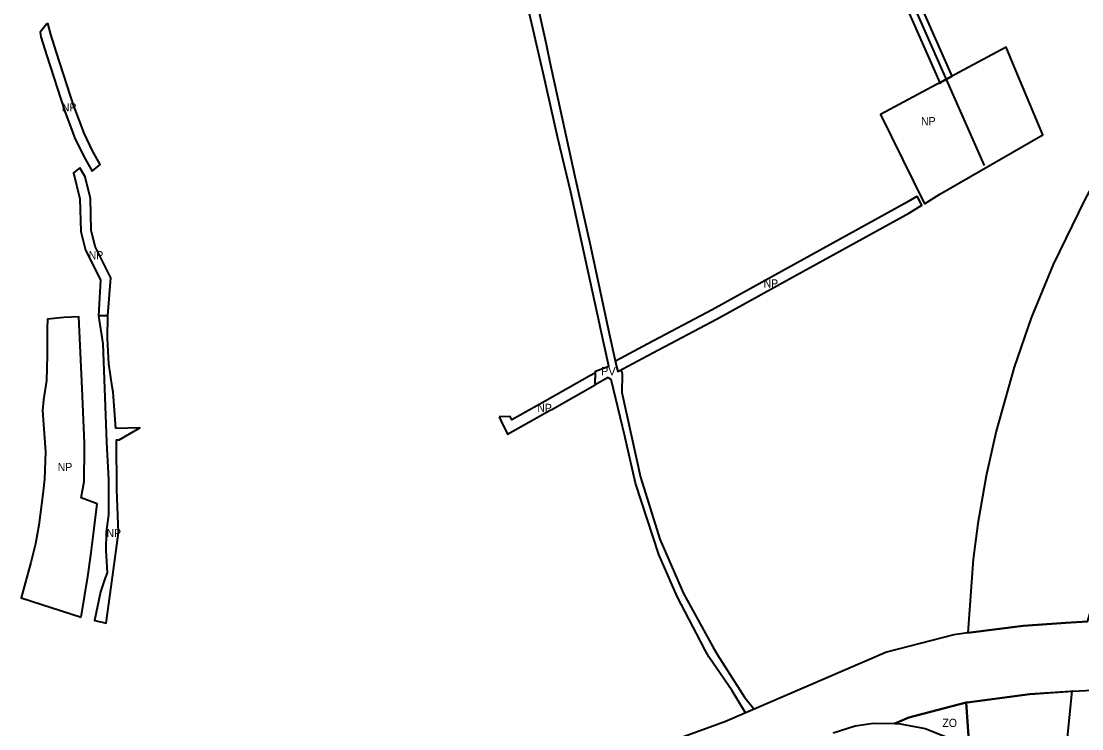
# Model space of a CAD drawing. Extents: x -650276 to -642489, y -1074311 to -1066658.
# Drawn here: x -649415 to -647873, y -1069108 to -1068079 of the extents above; entities that cross this region are included whole.
import ezdxf

# ---------------------------------------------------------------- set-up
doc = ezdxf.new("R2010")
doc.units = 0
doc.header["$LTSCALE"] = 4.8
doc.header["$PDMODE"] = 32
doc.header["$PDSIZE"] = 2.4
for name, color, linetype, lineweight in [('15', 7, 'Continuous', 35), ('24', 7, 'Continuous', 35), ('25', 7, 'Continuous', 35), ('42', 7, 'Continuous', 35), ('48', 7, 'Continuous', 35), ('54', 7, 'Continuous', 35)]:
    doc.layers.add(name, color=color, linetype=linetype, lineweight=lineweight)
doc.layers.add('62', color=7, linetype='Continuous')

msp = doc.modelspace()

# ---------------------------------------------------------------- linework, layer by layer
at = {"layer": '15'}
for points in [[(-648668.92, -1068032.96), (-648651.89, -1068111.95), (-648649.74, -1068121.95), (-648644.73, -1068145.27), (-648630.99, -1068209.19), (-648610.14, -1068304.32), (-648587.39, -1068405.82), (-648559.91, -1068532.62), (-648549.84, -1068578.65), (-648547.25, -1068588.14), (-648542.93, -1068586.13), (-648541.74, -1068589.27)], [(-648349.419, -1069079.223), (-648362.06, -1069084.664), (-648381.44, -1069052.48), (-648415.29, -1069003.16), (-648419.78, -1068994.25), (-648427.21, -1068980.13), (-648461.22, -1068915.44), (-648488.09, -1068854.16), (-648521.92, -1068750.34), (-648537.29, -1068681.95), (-648557.4, -1068599.9), (-648559.44, -1068598.37), (-648561.49, -1068596.84), (-648580.66, -1068607.64), (-648579.97, -1068587.39), (-648560.79, -1068580.12), (-648572.95, -1068522.97), (-648573.96, -1068518.34), (-648594.38, -1068425.02), (-648615.87, -1068327.3), (-648634.84, -1068248.76), (-648655.88, -1068153.63), (-648662.71, -1068124.76), (-648677.61, -1068061.74)], [(-648541.74, -1068589.27), (-648541.25, -1068592.3), (-648541.89, -1068618.64), (-648514.35, -1068741.53), (-648486.25, -1068831.83), (-648451.76, -1068910.91), (-648409.15, -1068988.44), (-648402.76, -1069000.2), (-648363.11, -1069061.72), (-648349.419, -1069079.223)]]:
    msp.add_lwpolyline(points, dxfattribs=at)
at = {"layer": '24'}
for points in [[(-647864.531, -1068951.823), (-647895.901, -1068953.392), (-647958.168, -1068957.73), (-648038.596, -1068968.281), (-648038.759, -1068968.54)], [(-648038.759, -1068968.54), (-648038.746, -1068968.301), (-648058.764, -1068970.927), (-648156.739, -1068996.273), (-648392.002, -1069097.554), (-648451.865, -1069119.456)], [(-648040.705, -1069069.547), (-648039.666, -1069069.279), (-647948.18, -1069057.276), (-647886.615, -1069053.052), (-647856.541, -1069051.548), (-647848.615, -1069051.679), (-647842.888, -1069051.774), (-647814.401, -1069052.246)], [(-648234.22, -1069113.6), (-648202.46, -1069103.3), (-648175.65, -1069099.64), (-648144.866, -1069099.987), (-648124.327, -1069091.181), (-648040.705, -1069069.547)]]:
    msp.add_lwpolyline(points, dxfattribs=at)
at = {"layer": '25'}
msp.add_line((-648038.596, -1068968.281), (-647958.168, -1068957.73), dxfattribs=at)
for points in [[(-647801.797, -1068219.34), (-647843.6, -1068292.629), (-647868.214, -1068337.803), (-647914.339, -1068432.512), (-647946.187, -1068510.254), (-647971.074, -1068581.98), (-647997.27, -1068674.747), (-648011.775, -1068739.718), (-648023.914, -1068809.332), (-648030.73, -1068861.213), (-648038.596, -1068968.281)], [(-647958.168, -1068957.73), (-647895.901, -1068953.392), (-647864.531, -1068951.823), (-647847.197, -1068897.199), (-647847.034, -1068896.687), (-647846.989, -1068896.545)], [(-647948.18, -1069057.276), (-648039.666, -1069069.279), (-648040.705, -1069069.548), (-648036.291, -1069139.458)], [(-647886.615, -1069053.052), (-647889.927, -1069053.218), (-647948.18, -1069057.276)], [(-647893.553, -1069279.017), (-647896.67, -1069213.573), (-647896.362, -1069149.171), (-647886.615, -1069053.052)]]:
    msp.add_lwpolyline(points, dxfattribs=at)
at = {"layer": '42'}
msp.add_lwpolyline([(-648100.37, -1069107.1), (-648065.16, -1069121.12), (-648048.06, -1069130.81), (-648036.291, -1069139.458), (-648040.705, -1069069.547), (-648124.327, -1069091.181), (-648144.867, -1069099.987), (-648139.27, -1069100.05), (-648100.37, -1069107.1)], close=True, dxfattribs=at)
at = {"layer": '48'}
for points in [[(-648238.748, -1067756.759), (-648256.499, -1067766.091), (-648079.002, -1068168.139)], [(-648079.002, -1068168.139), (-648061.329, -1068158.649), (-648232.676, -1067770.513)], [(-649302.681, -1068507.363), (-649296.55, -1068548.09), (-649290.93, -1068690.93), (-649287.98, -1068745.74), (-649288.19, -1068786.39), (-649288.24, -1068796.6), (-649291.64, -1068821.88), (-649291.87, -1068848.02), (-649290.28, -1068880.82), (-649293.33, -1068889.65), (-649299.91, -1068908.66), (-649308.65, -1068950), (-649293.04, -1068953.81), (-649291.32, -1068954.23), (-649281.01, -1068876.69), (-649273.66, -1068822.58), (-649275.96, -1068759.73), (-649276.43, -1068688.29), (-649276.474, -1068687.673), (-649272.755, -1068687.618)], [(-649277.655, -1068670.983), (-649281.4, -1068618.05), (-649282.97, -1068610.04), (-649287.71, -1068577.14), (-649289.74, -1068540.2), (-649289.24, -1068506.8), (-649302.681, -1068507.363)], [(-649272.755, -1068687.618), (-649272.69, -1068687.58), (-649242.507, -1068669.925), (-649277.655, -1068670.983)]]:
    msp.add_lwpolyline(points, dxfattribs=at)
for points in [[(-649376.467, -1068081.552), (-649377.77, -1068082.44), (-649387.46, -1068094.51), (-649386.74, -1068101.31), (-649377.81, -1068129), (-649352.11, -1068208.65), (-649339.94, -1068241.13), (-649337.52, -1068247.59), (-649324.66, -1068274.3), (-649319.551, -1068283.382), (-649312.087, -1068296.653), (-649300.305, -1068287.002), (-649311.352, -1068267.362), (-649323.711, -1068241.693), (-649337.178, -1068205.751), (-649337.942, -1068203.713), (-649363.534, -1068124.395), (-649371.987, -1068098.185)], [(-648101.42, -1068344.28), (-648079.33, -1068330.03), (-647929.45, -1068244.16), (-647971.35, -1068144.48), (-647982.969, -1068116.575), (-648165.28, -1068214.465)], [(-649330.038, -1068291.976), (-649339.046, -1068299.359), (-649329.644, -1068336.779), (-649328.386, -1068384.468), (-649321.727, -1068411.472), (-649299.894, -1068454.728), (-649302.681, -1068507.363), (-649289.24, -1068506.8), (-649284.59, -1068451.76), (-649307.57, -1068406.23), (-649313.42, -1068382.51), (-649314.27, -1068336.41), (-649314.693, -1068334.727), (-649322.18, -1068304.93)], [(-648112.198, -1068333.037), (-648112.92, -1068333.424), (-648131.034, -1068344.388), (-648305.242, -1068440.3), (-648410.111, -1068498.408), (-648503.768, -1068547.914), (-648551.041, -1068573.16), (-648549.84, -1068578.65), (-648547.25, -1068588.14), (-648496.73, -1068561.16), (-648402.97, -1068511.6), (-648297.99, -1068453.43), (-648123.53, -1068357.38), (-648105.49, -1068346.46)], [(-649327.679, -1068945.222), (-649318.13, -1068886.42), (-649314.07, -1068855.33), (-649310.01, -1068824.2), (-649304.66, -1068780.33), (-649327.8, -1068771.82), (-649323.68, -1068748.06), (-649323.1, -1068699.28), (-649323.02, -1068692.1), (-649326.53, -1068612.89), (-649331.151, -1068508.557), (-649353.17, -1068509.48), (-649376.77, -1068511.96), (-649377.52, -1068525.1), (-649377.56, -1068564.89), (-649378.08, -1068601.24), (-649382.46, -1068629.34), (-649384.31, -1068644.92), (-649379.97, -1068704.98), (-649381.06, -1068744.69), (-649383.78, -1068766.6), (-649389.34, -1068811.43), (-649394.48, -1068838.89), (-649401.31, -1068865.78), (-649415.09, -1068917.1)], [(-648720.238, -1068654.205), (-648717.32, -1068660.24), (-648708.14, -1068679.23), (-648645.69, -1068644.27), (-648643.654, -1068643.123), (-648580.66, -1068607.64), (-648580.062, -1068590.087), (-648588.022, -1068594.571), (-648653.034, -1068631.191), (-648701.568, -1068658.36), (-648703.816, -1068653.711)]]:
    msp.add_lwpolyline(points, close=True, dxfattribs=at)
msp.add_point((-648079.002, -1068168.139), dxfattribs=at)
at = {"layer": '54'}
msp.add_lwpolyline([(-648383.36, -1067413.938), (-648264.607, -1067722.965), (-648014.937, -1068288.491)], dxfattribs=at)

# ---------------------------------------------------------------- texts
at = {"layer": '62', "width": 0.95}
for s, p in [('NP', (-649355.985, -1068209.967)), ('NP', (-648106.583, -1068230.041)), ('NP', (-649316.985, -1068424.967)), ('NP', (-648335.583, -1068466.041)), ('NP', (-648664.583, -1068647.041)), ('NP', (-649361.985, -1068732.967)), ('NP', (-649290.985, -1068828.967)), ('ZO', (-648075.473, -1069105.058))]:
    msp.add_text(s, height=12, dxfattribs=at).set_placement(p)
at = {"layer": '62'}
msp.add_text('PV', height=12, dxfattribs=at).set_placement((-648571.984, -1068593.692))

doc.saveas('drawing.dxf')
